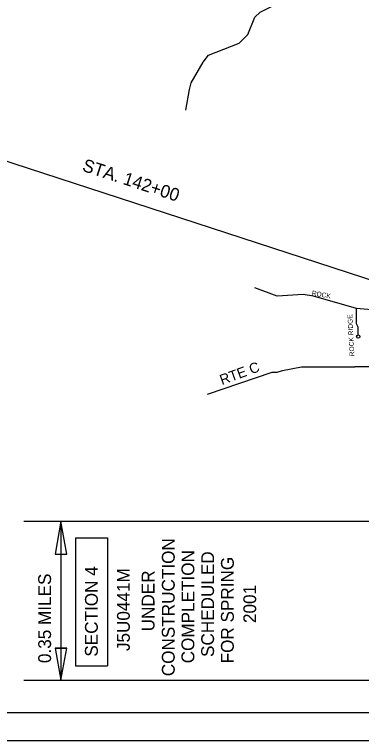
# Model space of a CAD drawing. Extents: x 5.01 to 9.58, y 0.27 to 3.39.
# Drawn here: x 6.043 to 6.828, y 0.321 to 1.964 of the extents above; entities that cross this region are included whole.
import ezdxf

# ---------------------------------------------------------------- set-up
doc = ezdxf.new("R2010")
doc.units = 0
for name, color, linetype in [('Level 7', 7, 'Continuous'), ('MO_001_VIEW_99', 7, 'Continuous'), ('MO_001_VIEW_PV', 7, 'Continuous')]:
    doc.layers.add(name, color=color, linetype=linetype)

msp = doc.modelspace()

# ---------------------------------------------------------------- linework, layer by layer
at = {"layer": 'Level 7'}
for p, q in [((5.7734, 1.7142), (7.1715, 1.2576)), ((6.064, 0.8169), (6.9244, 0.8169)), ((6.1479, 0.8169), (6.1479, 0.4568)), ((6.1804, 0.7796), (6.1804, 0.4898)), ((6.1804, 0.7796), (6.2528, 0.7796)), ((6.2528, 0.7796), (6.2528, 0.4898)), ((6.1351, 0.5293), (6.1608, 0.5293)), ((6.1351, 0.5293), (6.1479, 0.4568)), ((6.1479, 0.4568), (6.1608, 0.5293)), ((6.1804, 0.4898), (6.2528, 0.4898)), ((6.064, 0.4568), (7.3877, 0.4568)), ((5.3044, 0.3838), (8.2666, 0.3838))]:
    msp.add_line(p, q, dxfattribs=at)
for points in [[(6.1479, 0.8169), (6.1348, 0.7426), (6.1611, 0.7426)], [(6.1479, 0.8169), (6.1348, 0.7426), (6.1611, 0.7426)], [(6.1351, 0.5293), (6.1479, 0.4568), (6.1608, 0.5293)]]:
    msp.add_lwpolyline(points, close=True, dxfattribs=at)
at = {"layer": 'MO_001_VIEW_99'}
msp.add_line((5.014, 0.3206), (9.5796, 0.3206), dxfattribs=at)
at = {"layer": 'MO_001_VIEW_PV'}
for p, q in [((6.8594, 1.2949), (6.8165, 1.2987)), ((6.7736, 1.1662), (6.8126, 1.1662)), ((6.9062, 1.1662), (6.8126, 1.1662))]:
    msp.add_line(p, q, dxfattribs=at)
for points in [[(6.4306, 1.747), (6.4384, 1.7938), (6.4423, 1.8094), (6.4696, 1.8562), (6.4813, 1.8718), (6.5514, 1.899), (6.5709, 1.9185), (6.5865, 1.9575), (6.5982, 1.9692), (6.723, 2.0316), (6.7619, 2.0394), (6.8048, 2.0394), (6.8399, 2.0355), (6.8984, 2.0043), (6.9257, 1.9965), (6.9997, 1.9965), (7.0376, 1.993)], [(6.8165, 1.2987), (6.719, 1.326), (6.6957, 1.3299), (6.6372, 1.326), (6.5865, 1.3455)], [(6.8204, 1.2384), (6.8204, 1.2559), (6.8165, 1.2637), (6.8165, 1.2987)], [(6.4794, 1.1045), (6.6255, 1.1545), (6.6372, 1.1545)], [(6.6372, 1.1545), (6.6489, 1.1584), (6.6918, 1.1662), (6.7736, 1.1662)]]:
    msp.add_lwpolyline(points, dxfattribs=at)
msp.add_circle((6.8204, 1.2348), 0.00362, dxfattribs=at)

# ---------------------------------------------------------------- texts
at = {"layer": 'Level 7'}
for s, height, rotation, p in [('STA. 142+00', 0.028993, 341.9135, (6.1941, 1.6104)), ('CONSTRUCTION', 0.028993, 90, (6.4052, 0.4661)), ('COMPLETION', 0.02899, 90, (6.4496, 0.4952)), ('SCHEDULED', 0.02899, 90, (6.4942, 0.5096)), ('FOR SPRING', 0.02899, 90, (6.5389, 0.4951)), ('SECTION 4', 0.02899, 90, (6.2312, 0.5103)), ('J5U0441M', 0.02899, 90, (6.3036, 0.5229)), ('0.35 MILES', 0.02899, 90, (6.1254, 0.4958)), ('UNDER', 0.02899, 90, (6.3595, 0.5676)), ('2001', 0.02899, 90, (6.5895, 0.5864))]:
    msp.add_text(s, height=height, rotation=rotation, dxfattribs=at).set_placement(p)
at = {"layer": 'MO_001_VIEW_PV'}
for s, height, rotation, p in [('ROCK', 0.01087, 350, (6.7147, 1.3284)), ('ROCK RIDGE', 0.01087, 93, (6.8119, 1.1905)), ('RTE C', 0.02319, 20, (6.5121, 1.125))]:
    msp.add_text(s, height=height, rotation=rotation, dxfattribs=at).set_placement(p)

doc.saveas('drawing.dxf')
